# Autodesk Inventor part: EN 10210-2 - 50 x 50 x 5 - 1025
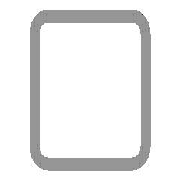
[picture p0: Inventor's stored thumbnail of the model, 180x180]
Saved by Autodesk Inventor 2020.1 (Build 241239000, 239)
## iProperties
_CCFamilyMember: 16
_CCFamilyDisplayName: DIN EN 10210-2 (USAS B17.1 quadratisch) - Rohrleitung — In Klammern angegebene Größen wurden aufgehoben
_FrameMemberDoc: Frame Member File
_Version: 15.0.0
_GetPNFromCC: 1
IsCustomPart: 1
Created: 2019-01
Part Number: EN 10210-2 - 50 x 50 x 5 - 1025
Material: Stahl, weich
Description: Rohrleitung
Document SubType Name: Modeling
Standard: DIN
Designer: lutzd
Standard Revision: 2006-07
Standards Organization: DIN
Language: de-DE
Size Designation: 50 x 50 x 5
Categories: <MemberInstance><Categories><Category DisplayName="Profile" InternalName="089c4875-fa83-4c05-b084-43b9cc11f5ed" Mnemonic="GRDR"><CategoryParameter DisplayName="
Stock Number: 50 x 50 x 5
Mass: 7025.78 g
Surface Area: 3487.5 cm^2
Volume: 895.004 cm^3
Density: 7.85 g/cm^3
Appearance: Halbpoliert
G_W: 50,000 mm
G_H: 50,000 mm
Dimensions: 50x50x1025 mm
Mass: 7,026 kg
DocNumber: ADSK-014204
Folder: .
+CA8061A1-F4AE-4834-9679-8F51B78A68D9+SCHNITTDETAIL1: Schnittwinkel 90,00 grd
+0348F3BE-899A-4CA6-80F1-09895A799464+SCHNITTDETAIL3: Schnittwinkel 90,00 grd
G_L: 1025,000 mm
Title: Profil-Bauteil
Author: lutzd
Revision Number: -
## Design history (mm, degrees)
node "Startebene"
node "Endebene"
sketch "Skizze"
  geometry: L1 (-25, -17.5)-(-25, 17.5); L2 (-17.5, 25)-(17.5, 25); L3 (25, 17.5)-(25, -17.5); L4 (17.5, -25)-(-17.5, -25); L5 (-15, 20)-(15, 20); L6 (20, 15)-(20, -15); L7 (15, -20)-(-15, -20); L8 (-20, -15)-(-20, 15); L9 (0, 37.175)-(0, -37.175) reference; L10 (-37.175, 0)-(37.175, 0) reference; A1 r 7.5 centre (-17.5, -17.5) between (-25, -17.5) and (-17.5, -25); A2 r 7.5 centre (-17.5, 17.5) between (-17.5, 25) and (-25, 17.5); A3 r 7.5 centre (17.5, 17.5) between (25, 17.5) and (17.5, 25); A4 r 7.5 centre (17.5, -17.5) between (17.5, -25) and (25, -17.5); A5 r 5 centre (-15, -15) between (-20, -15) and (-15, -20); A6 r 5 centre (-15, 15) between (-15, 20) and (-20, 15); A7 r 5 centre (15, 15) between (20, 15) and (15, 20); A8 r 5 centre (15, -15) between (15, -20) and (20, -15)
  constraints: 16 end point, 16 point on circle, 16 tangent, 8 centre point, 6 equal radius, 4 parallel, 2 perpendicular, 2 other
  dimensions: "d7" = 7.5 radius of A1 (= G_IR); "d10" = 50 distance between parallel lines of L2 L4 (= G_H); "d11" = 50 distance between parallel lines of L1 L3 (= G_W); "d12" = 5 distance between parallel lines of L3 L6 (= G_T); "d15" = 25 distance between parallel lines of L2 L10 (= 0.5 x d10); "d16" = 25 distance between parallel lines of L9 L3 (= 0.5 x d11); "d19" = 5 radius of A5 (= G_T); "d20" = 5 distance between parallel lines of L4 L7 (= G_T)
extrude "Körper" new body sketch "Skizze" stored distance "d3" = 1025 (= G_L); taper "d4" = 0 deg
node "Driven Length"
  sketch "Sketch3"
    geometry: L1 (0, 0)-(10, 0) reference
    constraints: 2 end point, 1 horizontal
  workplane "Work Plane3"
  sketch "Sketch4"
    geometry: L1 (-2, 25)-(12, 25) reference; L2 (-2, 1050)-(12, 1050) reference
    dimensions: "d18" = 1025 distance between parallel lines of L1 L2 (derived)
workplane "Arbeitsebene4"
feature "Trennen1"
workplane "Arbeitsebene6"
feature "Trennen3"
body "Solid1"
other parameters: "G_W" = 50 [user parameter; used in 1 equation term], "G_H" = 50 [user parameter; used in 1 equation term], "G_T" = 5 [user parameter; used in 3 equation terms], "G_IR" = 7.5 [user parameter; used in 1 equation term], "G_L" = 1025 (= d18) [user parameter; used in 1 equation term], "G_OFFSET_START" = -25 [user parameter; used in 1 equation term], "d13" = 25 (= -G_OFFSET_START), "d17" = 90 deg
